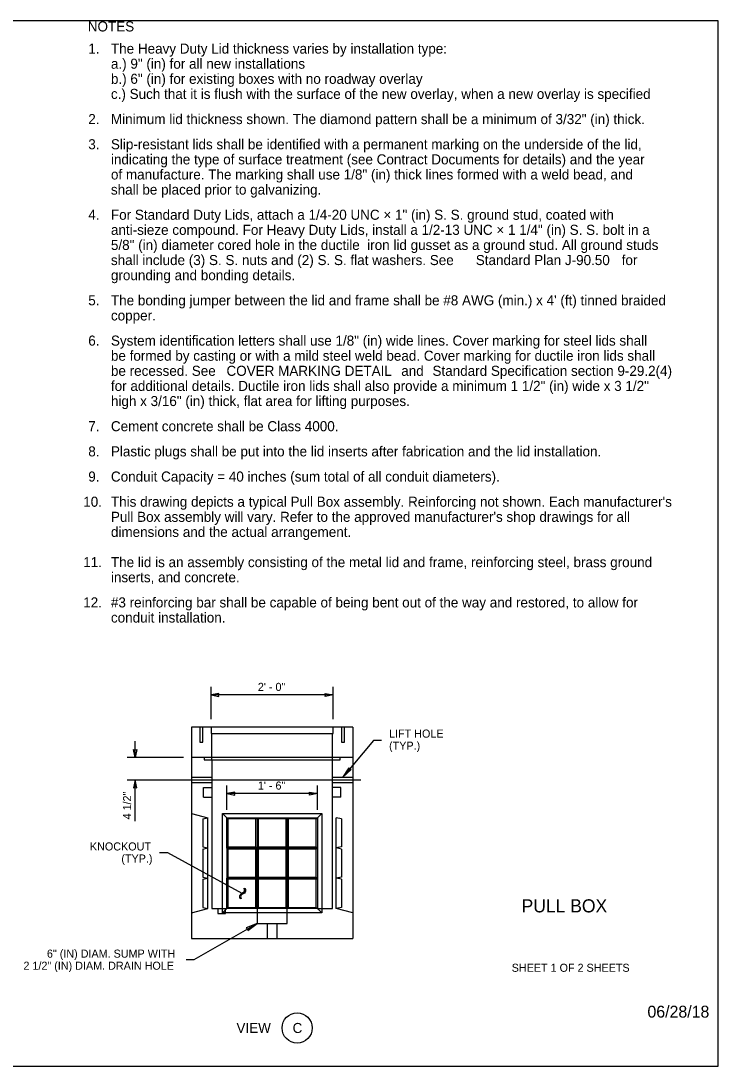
# Model space of a CAD drawing. Extents: x 99862 to 103151, y 100000 to 105076.
# Drawn here: x 101766 to 103151, y 100000 to 102076 of the extents above; entities that cross this region are included whole.
import ezdxf

# ---------------------------------------------------------------- set-up
doc = ezdxf.new("R2010")
doc.units = 0
for name, color, linetype in [('Level 1', 7, 'Continuous'), ('Level 15', 7, 'Continuous'), ('Level 2', 7, 'Continuous'), ('Level 20', 7, 'Continuous'), ('Level 3', 7, 'Continuous'), ('Level 50', 7, 'Continuous'), ('Level 60', 7, 'Continuous'), ('Level 62', 7, 'Continuous')]:
    doc.layers.add(name, color=color, linetype=linetype)

msp = doc.modelspace()

# ---------------------------------------------------------------- linework, layer by layer
at = {"layer": 'Level 1'}
msp.add_lwpolyline([(99862, 99999.5), (103151, 99999.5), (103151, 102075.5), (99862, 102075.5)], close=True, dxfattribs=at)
at = {"layer": 'Level 15'}
for p, q in [((102144.1, 100688.7), (102144.1, 100752.7)), ((102386.6, 100688.7), (102386.6, 100752.7)), ((102386.6, 100736.7), (102144.1, 100736.7)), ((101993.3, 100612.7), (101993.3, 100644.7)), ((102466.8, 100646.4), (102405.3, 100572.7)), ((102482.8, 100646.4), (102466.8, 100646.4)), ((102089.3, 100612.7), (101977.3, 100612.7)), ((102441.3, 100567.7), (101977.3, 100567.7)), ((101993.3, 100485.7), (101993.3, 100567.7)), ((102175.3, 100508.7), (102175.3, 100556.7)), ((102355.3, 100508.7), (102355.3, 100556.7)), ((102355.3, 100540.7), (102175.3, 100540.7)), ((102041.7, 100423.8), (102057.7, 100423.8)), ((102057.7, 100423.8), (102205, 100342.7)), ((102200.9, 100336.1), (102201.1, 100337.8)), ((102201.2, 100334.3), (102200.9, 100336.1)), ((102201.1, 100337.8), (102201.8, 100339.4)), ((102202, 100332.5), (102201.2, 100334.3)), ((102201.8, 100339.4), (102203.6, 100341.5)), ((102203, 100336.8), (102202.8, 100335.5)), ((102202.8, 100335.5), (102203.1, 100333.8)), ((102203.5, 100338.1), (102203, 100336.8)), ((102203.1, 100333.8), (102203.8, 100331.4)), ((102204.7, 100339.5), (102203.5, 100338.1)), ((102203.6, 100341.5), (102207.2, 100344)), ((102206.8, 100341), (102204.7, 100339.5)), ((102210.2, 100343.3), (102206.8, 100341)), ((102207.2, 100344), (102209.2, 100345.4)), ((102209.2, 100345.4), (102210.1, 100346.6)), ((102210.7, 100349.6), (102209.7, 100353.1)), ((102209.7, 100353.1), (102211.6, 100352.1)), ((102210.1, 100346.6), (102210.6, 100347.9)), ((102211.8, 100345.2), (102210.2, 100343.3)), ((102210.6, 100347.9), (102210.7, 100349.6)), ((102211.6, 100352.1), (102212.3, 100350.1)), ((102212.4, 100346.7), (102211.8, 100345.2)), ((102212.3, 100350.1), (102212.6, 100348.3)), ((102212.6, 100348.3), (102212.4, 100346.7)), ((102203.8, 100331.4), (102202, 100332.5)), ((102110.6, 100210.9), (102235.3, 100282.7)), ((102094.6, 100210.9), (102110.6, 100210.9))]:
    msp.add_line(p, q, dxfattribs=at)
for points in [[(102144.1, 100736.7), (102159.8, 100733.6), (102159.1, 100736.7), (102159.8, 100739.7)], [(102386.6, 100736.7), (102370.8, 100733.6), (102371.6, 100736.7), (102370.8, 100739.7)], [(101993.3, 100612.7), (101990.2, 100628.4), (101993.3, 100627.6), (101996.4, 100628.4)], [(102405.3, 100572.7), (102422.2, 100588.3), (102419.3, 100589.4), (102417.6, 100592.1)], [(101993.3, 100567.7), (101990.2, 100551.9), (101993.3, 100552.7), (101996.4, 100551.9)], [(102175.3, 100540.7), (102191, 100537.6), (102190.3, 100540.7), (102191, 100543.7)], [(102355.3, 100540.7), (102339.6, 100537.6), (102340.3, 100540.7), (102339.6, 100543.7)], [(102235.3, 100282.7), (102214, 100273.9), (102216.4, 100271.8), (102217, 100268.7)]]:
    msp.add_lwpolyline(points, close=True, dxfattribs=at)
at = {"layer": 'Level 2'}
for p, q in [((102105.3, 100612.7), (102105.3, 100252.7)), ((102425.3, 100612.7), (102425.3, 100252.7)), ((102166.6, 100303.9), (102166.6, 100501.4)), ((102166.6, 100501.4), (102175.3, 100492.7)), ((102166.6, 100501.4), (102364, 100501.4)), ((102364, 100501.4), (102355.3, 100492.7)), ((102364, 100501.4), (102364, 100303.9)), ((102177.5, 100490.5), (102175.3, 100492.7)), ((102175.3, 100432.7), (102175.3, 100492.7)), ((102175.3, 100492.7), (102235.3, 100492.7)), ((102177.5, 100490.5), (102177.5, 100434.8)), ((102233.1, 100490.5), (102177.5, 100490.5)), ((102233.1, 100490.5), (102235.3, 100492.7)), ((102233.1, 100434.8), (102233.1, 100490.5)), ((102237.5, 100490.5), (102235.3, 100492.7)), ((102235.3, 100492.7), (102295.3, 100492.7)), ((102235.3, 100492.7), (102235.3, 100432.7)), ((102293.1, 100490.5), (102237.5, 100490.5)), ((102237.5, 100490.5), (102237.5, 100434.8)), ((102293.1, 100490.5), (102295.3, 100492.7)), ((102293.1, 100434.8), (102293.1, 100490.5)), ((102297.5, 100490.5), (102295.3, 100492.7)), ((102295.3, 100432.7), (102295.3, 100492.7)), ((102295.3, 100492.7), (102355.3, 100492.7)), ((102297.5, 100490.5), (102297.5, 100434.8)), ((102353.1, 100490.5), (102297.5, 100490.5)), ((102353.1, 100490.5), (102355.3, 100492.7)), ((102353.1, 100434.8), (102353.1, 100490.5)), ((102355.3, 100492.7), (102355.3, 100432.7)), ((102177.5, 100434.8), (102175.3, 100432.7)), ((102177.5, 100430.5), (102175.3, 100432.7)), ((102235.3, 100432.7), (102175.3, 100432.7)), ((102175.3, 100432.7), (102175.3, 100372.7)), ((102177.5, 100434.8), (102233.1, 100434.8)), ((102233.1, 100430.5), (102177.5, 100430.5)), ((102177.5, 100430.5), (102177.5, 100374.8)), ((102233.1, 100434.8), (102235.3, 100432.7)), ((102233.1, 100430.5), (102235.3, 100432.7)), ((102233.1, 100374.8), (102233.1, 100430.5)), ((102237.5, 100434.8), (102235.3, 100432.7)), ((102237.5, 100430.5), (102235.3, 100432.7)), ((102235.3, 100432.7), (102295.3, 100432.7)), ((102235.3, 100372.7), (102235.3, 100432.7)), ((102237.5, 100434.8), (102293.1, 100434.8)), ((102293.1, 100430.5), (102237.5, 100430.5)), ((102237.5, 100430.5), (102237.5, 100374.8)), ((102293.1, 100434.8), (102295.3, 100432.7)), ((102293.1, 100430.5), (102295.3, 100432.7)), ((102293.1, 100374.8), (102293.1, 100430.5)), ((102297.5, 100434.8), (102295.3, 100432.7)), ((102295.3, 100432.7), (102355.3, 100432.7)), ((102297.5, 100430.5), (102295.3, 100432.7)), ((102295.3, 100372.7), (102295.3, 100432.7)), ((102297.5, 100434.8), (102353.1, 100434.8)), ((102353.1, 100430.5), (102297.5, 100430.5)), ((102297.5, 100430.5), (102297.5, 100374.8)), ((102353.1, 100434.8), (102355.3, 100432.7)), ((102353.1, 100430.5), (102355.3, 100432.7)), ((102353.1, 100374.8), (102353.1, 100430.5)), ((102355.3, 100432.7), (102355.3, 100372.7)), ((102177.5, 100374.8), (102175.3, 100372.7)), ((102177.5, 100374.8), (102233.1, 100374.8)), ((102233.1, 100374.8), (102235.3, 100372.7)), ((102237.5, 100374.8), (102235.3, 100372.7)), ((102237.5, 100374.8), (102293.1, 100374.8)), ((102293.1, 100374.8), (102295.3, 100372.7)), ((102297.5, 100374.8), (102295.3, 100372.7)), ((102297.5, 100374.8), (102353.1, 100374.8)), ((102353.1, 100374.8), (102355.3, 100372.7)), ((102175.3, 100312.7), (102175.3, 100372.7)), ((102175.3, 100372.7), (102235.3, 100372.7)), ((102177.5, 100370.5), (102175.3, 100372.7)), ((102177.5, 100370.5), (102177.5, 100314.8)), ((102233.1, 100370.5), (102177.5, 100370.5)), ((102233.1, 100370.5), (102235.3, 100372.7)), ((102233.1, 100314.8), (102233.1, 100370.5)), ((102235.3, 100312.7), (102235.3, 100372.7)), ((102235.3, 100372.7), (102295.3, 100372.7)), ((102237.5, 100370.5), (102235.3, 100372.7)), ((102237.5, 100370.5), (102237.5, 100314.8)), ((102293.1, 100370.5), (102237.5, 100370.5)), ((102293.1, 100370.5), (102295.3, 100372.7)), ((102293.1, 100314.8), (102293.1, 100370.5)), ((102295.3, 100312.7), (102295.3, 100372.7)), ((102297.5, 100370.5), (102295.3, 100372.7)), ((102295.3, 100372.7), (102355.3, 100372.7)), ((102297.5, 100370.5), (102297.5, 100314.8)), ((102353.1, 100370.5), (102297.5, 100370.5)), ((102353.1, 100370.5), (102355.3, 100372.7)), ((102353.1, 100314.8), (102353.1, 100370.5)), ((102355.3, 100372.7), (102355.3, 100312.7)), ((102166.6, 100303.9), (102175.3, 100312.7)), ((102177.5, 100314.8), (102175.3, 100312.7)), ((102235.3, 100312.7), (102175.3, 100312.7)), ((102177.5, 100314.8), (102233.1, 100314.8)), ((102233.1, 100314.8), (102235.3, 100312.7)), ((102237.5, 100314.8), (102235.3, 100312.7)), ((102295.3, 100312.7), (102235.3, 100312.7)), ((102237.5, 100314.8), (102293.1, 100314.8)), ((102293.1, 100314.8), (102295.3, 100312.7)), ((102297.5, 100314.8), (102295.3, 100312.7)), ((102355.3, 100312.7), (102295.3, 100312.7)), ((102297.5, 100314.8), (102353.1, 100314.8)), ((102353.1, 100314.8), (102355.3, 100312.7)), ((102364, 100303.9), (102355.3, 100312.7)), ((102364, 100303.9), (102166.6, 100303.9)), ((102105.3, 100252.7), (102425.3, 100252.7))]:
    msp.add_line(p, q, dxfattribs=at)
at = {"layer": 'Level 20'}
msp.add_circle((102315, 100075.2), 30, dxfattribs=at)
at = {"layer": 'Level 3'}
for p, q in [((102425.3, 100672.7), (102105.3, 100672.7)), ((102105.3, 100672.7), (102105.3, 100612.7)), ((102425.3, 100672.7), (102425.3, 100612.7)), ((102425.3, 100612.7), (102105.3, 100612.7))]:
    msp.add_line(p, q, dxfattribs=at)
at = {"layer": 'Level 50'}
for p, q in [((102121.6, 100672.7), (102121.6, 100642.7)), ((102127.8, 100642.7), (102127.8, 100672.7)), ((102144.1, 100672.7), (102144.1, 100660.2)), ((102386.6, 100660.2), (102386.6, 100672.7)), ((102402.8, 100672.7), (102402.8, 100642.7)), ((102409.1, 100642.7), (102409.1, 100672.7)), ((102144.1, 100660.2), (102386.6, 100660.2)), ((102145.3, 100607.7), (102145.3, 100660.2)), ((102385.3, 100607.7), (102385.3, 100660.2)), ((102121.6, 100642.7), (102127.8, 100642.7)), ((102402.8, 100642.7), (102409.1, 100642.7)), ((102130.3, 100612.7), (102130.3, 100607.7)), ((102130.3, 100607.7), (102400.3, 100607.7)), ((102145.3, 100607.7), (102145.3, 100312.7)), ((102385.3, 100312.7), (102385.3, 100607.7)), ((102400.3, 100607.7), (102400.3, 100612.7)), ((102145.3, 100572.7), (102105.3, 100572.7)), ((102105.3, 100562.7), (102145.3, 100562.7)), ((102425.3, 100572.7), (102385.3, 100572.7)), ((102385.3, 100562.7), (102425.3, 100562.7)), ((102129.1, 100533.9), (102129.1, 100552.7)), ((102129.1, 100552.7), (102145.3, 100552.7)), ((102401.6, 100552.7), (102385.3, 100552.7)), ((102401.6, 100533.9), (102401.6, 100552.7)), ((102129.1, 100533.9), (102145.3, 100533.9)), ((102401.6, 100533.9), (102385.3, 100533.9)), ((102105.3, 100501.4), (102137.8, 100492.7)), ((102127.8, 100490.5), (102137.8, 100492.7)), ((102127.8, 100490.5), (102127.8, 100434.8)), ((102137.8, 100432.7), (102137.8, 100492.7)), ((102402.8, 100490.5), (102392.8, 100492.7)), ((102392.8, 100432.7), (102392.8, 100492.7)), ((102402.8, 100490.5), (102402.8, 100434.8)), ((102127.8, 100434.8), (102137.8, 100432.7)), ((102127.8, 100430.5), (102137.8, 100432.7)), ((102127.8, 100430.5), (102127.8, 100374.8)), ((102137.8, 100372.7), (102137.8, 100432.7)), ((102402.8, 100434.8), (102392.8, 100432.7)), ((102402.8, 100430.5), (102392.8, 100432.7)), ((102392.8, 100372.7), (102392.8, 100432.7)), ((102402.8, 100430.5), (102402.8, 100374.8)), ((102127.8, 100374.8), (102137.8, 100372.7)), ((102402.8, 100374.8), (102392.8, 100372.7)), ((102127.8, 100370.5), (102137.8, 100372.7)), ((102127.8, 100370.5), (102127.8, 100314.8)), ((102137.8, 100312.7), (102137.8, 100372.7)), ((102402.8, 100370.5), (102392.8, 100372.7)), ((102392.8, 100312.7), (102392.8, 100372.7)), ((102402.8, 100370.5), (102402.8, 100314.8)), ((102105.3, 100303.9), (102137.8, 100312.7)), ((102127.8, 100314.8), (102137.8, 100312.7)), ((102145.3, 100312.7), (102175.3, 100312.7)), ((102157.8, 100312.7), (102157.8, 100302.7)), ((102172.8, 100302.7), (102172.8, 100312.7)), ((102235.3, 100312.7), (102235.3, 100282.7)), ((102295.3, 100282.7), (102295.3, 100312.7)), ((102355.3, 100312.7), (102385.3, 100312.7)), ((102402.8, 100314.8), (102392.8, 100312.7)), ((102425.3, 100303.9), (102392.8, 100312.7)), ((102157.8, 100302.7), (102172.8, 100302.7)), ((102235.3, 100282.7), (102275.3, 100282.7)), ((102255.3, 100282.7), (102255.3, 100252.7)), ((102275.3, 100282.7), (102295.3, 100282.7)), ((102275.3, 100252.7), (102275.3, 100282.7))]:
    msp.add_line(p, q, dxfattribs=at)
at = {"layer": 'Level 60'}
msp.add_line((103151, 102075.5), (103151, 102075.5), dxfattribs=at)

# ---------------------------------------------------------------- texts
at = {"layer": 'Level 15'}
msp.add_text('06/28/18', height=23.62, dxfattribs=at).set_placement((103010.7, 100095.8))
at = {"layer": 'Level 20'}
for s, height, p in [('NOTES', 20, (101899.2, 102054.5)), ('1.', 20, (101900.2, 102010.5)), ('The Heavy Duty Lid thickness varies by installation type:', 20, (101945.2, 102010.5)), ('a.) 9" (in) for all new installations', 20, (101945.2, 101980.5)), ('b.) 6" (in) for existing boxes with no roadway overlay', 20, (101945.2, 101950.5)), ('c.) Such that it is flush with the surface of the new overlay, when a new overlay is specified', 20, (101945.2, 101920.5)), ('2.', 20, (101900.2, 101870.5)), ('Minimum lid thickness shown. The diamond pattern shall be a minimum of 3/32" (in) thick.', 20, (101945.2, 101870.5)), ('3.', 20, (101900.2, 101820.5)), ('Slip-resistant lids shall be identified with a permanent marking on the underside of the lid,', 20, (101945.2, 101820.5)), ('indicating the type of surface treatment (see Contract Documents for details) and the year', 20, (101945.2, 101790.5)), ('of manufacture. The marking shall use 1/8" (in) thick lines formed with a weld bead, and', 20, (101945.2, 101760.5)), ('shall be placed prior to galvanizing.', 20, (101945.2, 101730.5)), ('4.', 20, (101900.2, 101680.5)), ('For Standard Duty Lids, attach a 1/4-20 UNC × 1" (in) S. S. ground stud, coated with', 20, (101945.2, 101680.5)), ('anti-sieze compound. For Heavy Duty Lids, install a 1/2-13 UNC × 1 1/4" (in) S. S. bolt in a', 20, (101945.2, 101650.5)), ('5/8" (in) diameter cored hole in the ductile  iron lid gusset as a ground stud. All ground studs', 20, (101945.2, 101620.5)), ('shall include (3) S. S. nuts and (2) S. S. flat washers. See ', 20, (101945.2, 101590.5)), ('Standard Plan J-90.50', 20, (102669.8, 101590.5)), (' for', 20, (102952.1, 101590.5)), ('grounding and bonding details.', 20, (101945.2, 101560.5)), ('5.', 20, (101900.2, 101510.5)), ("The bonding jumper between the lid and frame shall be #8 AWG (min.) x 4' (ft) tinned braided", 20, (101945.2, 101510.5)), ('copper.', 20, (101945.2, 101480.5)), ('6.', 20, (101900.2, 101430.5)), ('System identification letters shall use 1/8" (in) wide lines. Cover marking for steel lids shall', 20, (101945.2, 101430.5)), ('be formed by casting or with a mild steel weld bead. Cover marking for ductile iron lids shall', 20, (101945.2, 101400.5)), ('be recessed. See ', 20, (101945.2, 101370.5)), ('COVER MARKING DETAIL', 20, (102174.7, 101370.5)), (' and ', 20, (102514.3, 101370.5)), ('Standard Specification section 9-29.2(4)', 20, (102583.8, 101370.5)), ('for additional details. Ductile iron lids shall also provide a minimum 1 1/2" (in) wide x 3 1/2"', 20, (101945.2, 101340.5)), ('high x 3/16" (in) thick, flat area for lifting purposes.', 20, (101945.2, 101310.5)), ('7.', 20, (101900.2, 101260.5)), ('Cement concrete shall be Class 4000.', 20, (101945.2, 101260.5)), ('8.', 20, (101900.2, 101210.5)), ('Plastic plugs shall be put into the lid inserts after fabrication and the lid installation.', 20, (101945.2, 101210.5)), ('9.', 20, (101900.2, 101160.5)), ('Conduit Capacity = 40 inches (sum total of all conduit diameters).', 20, (101945.2, 101160.5)), ('10.', 20, (101890.2, 101110.5)), ("This drawing depicts a typical Pull Box assembly. Reinforcing not shown. Each manufacturer's", 20, (101945.2, 101110.5)), ("Pull Box assembly will vary. Refer to the approved manufacturer's shop drawings for all", 20, (101945.2, 101080.5)), ('dimensions and the actual arrangement.', 20, (101945.2, 101050.5)), ('11.', 20, (101890.2, 100990.5)), ('The lid is an assembly consisting of the metal lid and frame, reinforcing steel, brass ground', 20, (101945.2, 100990.5)), ('inserts, and concrete.', 20, (101945.2, 100960.5)), ('12.', 20, (101890.2, 100910.5)), ('#3 reinforcing bar shall be capable of being bent out of the way and restored, to allow for', 20, (101945.2, 100910.5)), ('conduit installation.', 20, (101945.2, 100880.5)), ('2\' - 0"', 16, (102237, 100744.7)), ('LIFT HOLE', 16, (102497.6, 100651.9)), ('(TYP.)', 16, (102497.6, 100627.9)), ('1\' - 6"', 16, (102237, 100548.7)), ('VIEW', 20, (102194.5, 100065.4)), ('C', 20, (102306, 100065.2))]:
    msp.add_text(s, height=height, dxfattribs=at).set_placement(p)
for s, rotation, p in [('4 1/2"', 90, (101985.3, 100489.4)), ('KNOCKOUT', 360, (101903.5, 100427.8)), ('(TYP.)', 360, (101965.9, 100403.8)), ('6" (IN) DIAM. SUMP WITH', 360, (101818.1, 100214.9)), ('2 1/2" (IN) DIAM. DRAIN HOLE', 360, (101771.5, 100190.9))]:
    msp.add_text(s, height=16, rotation=rotation, dxfattribs=at).set_placement(p)
at = {"layer": 'Level 62'}
for s, height, p in [('PULL BOX', 26, (102760.7, 100304.8)), ('SHEET 1 OF 2 SHEETS', 16, (102741.1, 100186.8))]:
    msp.add_text(s, height=height, dxfattribs=at).set_placement(p)

doc.saveas('drawing.dxf')
